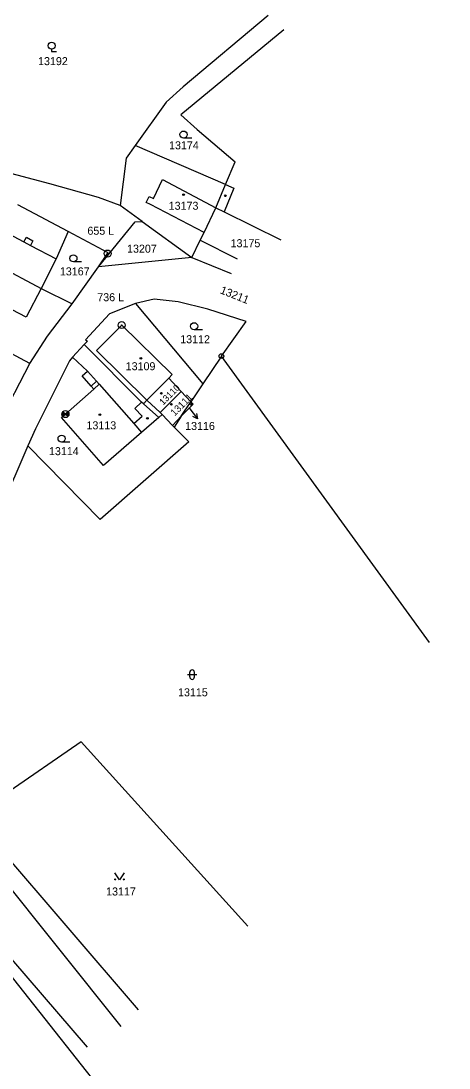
# Model space of a CAD drawing. Extents: x -822293 to -820259, y -1071573 to -1068794.
# Drawn here: x -820500.9 to -820409.9, y -1071370.4 to -1071147.9 of the extents above; entities that cross this region are included whole.
import ezdxf

# ---------------------------------------------------------------- set-up
doc = ezdxf.new("R2010")
doc.units = 0
for name, color, linetype in [('Vrstva 1', 7, 'Continuous'), ('Vrstva 10', 7, 'Continuous'), ('Vrstva 16', 7, 'Continuous'), ('Vrstva 17', 7, 'Continuous'), ('Vrstva 18', 7, 'Continuous'), ('Vrstva 19', 7, 'Continuous'), ('Vrstva 2', 7, 'Continuous'), ('Vrstva 24', 7, 'Continuous'), ('Vrstva 25', 7, 'Continuous'), ('Vrstva 3', 7, 'Continuous'), ('Vrstva 4', 7, 'Continuous')]:
    doc.layers.add(name, color=color, linetype=linetype)

msp = doc.modelspace()

# ---------------------------------------------------------------- linework, layer by layer
at = {"layer": 'Vrstva 1'}
for p, q in [((-820448.39, -1071146.76), (-820466.46, -1071161.95)), ((-820445.03, -1071149.78), (-820466.9, -1071167.9)), ((-820466.46, -1071161.95), (-820470.02, -1071165.17)), ((-820470.02, -1071165.17), (-820476.62, -1071174.38)), ((-820466.9, -1071167.9), (-820463.46, -1071171)), ((-820463.46, -1071171), (-820455.36, -1071177.84)), ((-820476.62, -1071174.38), (-820478.54, -1071177.06)), ((-820457.41, -1071182.67), (-820476.62, -1071174.38)), ((-820478.54, -1071177.06), (-820479.84, -1071187.11)), ((-820457.41, -1071182.67), (-820455.36, -1071177.84)), ((-820494.77, -1071182.54), (-820505.17, -1071179.75)), ((-820484.47, -1071185.46), (-820494.77, -1071182.54)), ((-820479.84, -1071187.11), (-820484.47, -1071185.46)), ((-820500.39, -1071187.63), (-820501.57, -1071187.01)), ((-820490.89, -1071192.65), (-820500.39, -1071187.63)), ((-820475.14, -1071190.53), (-820479.84, -1071187.11)), ((-820484.47, -1071200.14), (-820476.61, -1071190.6)), ((-820476.61, -1071190.6), (-820475.14, -1071190.53)), ((-820475.14, -1071190.53), (-820464.62, -1071198.17)), ((-820490.89, -1071192.65), (-820493.45, -1071198.44)), ((-820482.36, -1071197.15), (-820490.89, -1071192.65)), ((-820464.62, -1071198.17), (-820462.84, -1071194.51)), ((-820484.47, -1071200.14), (-820482.5, -1071197.34)), ((-820482.36, -1071197.15), (-820482.5, -1071197.34)), ((-820464.62, -1071198.17), (-820484.47, -1071200.14)), ((-820464.62, -1071198.17), (-820456.22, -1071201.54)), ((-820490.07, -1071207.98), (-820484.47, -1071200.14)), ((-820496.66, -1071204.76), (-820490.07, -1071207.98)), ((-820495.3, -1071214.89), (-820490.07, -1071207.98)), ((-820476.55, -1071207.91), (-820482.13, -1071210.12)), ((-820472.6, -1071207.05), (-820476.55, -1071207.91)), ((-820476.55, -1071207.91), (-820462.25, -1071225.04)), ((-820467.5, -1071207.56), (-820472.6, -1071207.05)), ((-820461.2, -1071209.17), (-820467.5, -1071207.56)), ((-820482.13, -1071210.12), (-820487.19, -1071215.63)), ((-820453.05, -1071211.75), (-820461.2, -1071209.17)), ((-820499.01, -1071220.67), (-820517.72, -1071210.75)), ((-820458.31, -1071219.13), (-820453.05, -1071211.75)), ((-820499.01, -1071220.67), (-820495.3, -1071214.89)), ((-820487.46, -1071216.64), (-820489.97, -1071219.33)), ((-820486.81, -1071215.95), (-820487.46, -1071216.64)), ((-820475.27, -1071228.92), (-820487.46, -1071216.64)), ((-820487.19, -1071215.63), (-820486.81, -1071215.95)), ((-820489.97, -1071219.33), (-820490.59, -1071220.12)), ((-820486.77, -1071222.33), (-820489.97, -1071219.33)), ((-820458.31, -1071219.13), (-820462.25, -1071225.04)), ((-820414.04, -1071279.95), (-820458.31, -1071219.13)), ((-820505.56, -1071233.12), (-820499.01, -1071220.67)), ((-820490.59, -1071220.12), (-820497.82, -1071234.6)), ((-820487.9, -1071223.33), (-820486.77, -1071222.33)), ((-820486, -1071225.47), (-820487.9, -1071223.33)), ((-820485.43, -1071226.12), (-820486, -1071225.47)), ((-820462.25, -1071225.04), (-820464.77, -1071228.82)), ((-820474.13, -1071228.51), (-820474.9, -1071229.29)), ((-820470.87, -1071231.52), (-820471.62, -1071232.17)), ((-820466.83, -1071231.91), (-820468.35, -1071234.19)), ((-820497.82, -1071234.6), (-820499.47, -1071238.21)), ((-820468.35, -1071234.19), (-820468.7, -1071233.83)), ((-820468.35, -1071234.19), (-820465.21, -1071237.36)), ((-820465.21, -1071237.36), (-820484.08, -1071253.85)), ((-820499.47, -1071238.21), (-820505.24, -1071251.73)), ((-820484.08, -1071253.85), (-820499.47, -1071238.21)), ((-820488.09, -1071301.05), (-820504.37, -1071312.23)), ((-820452.69, -1071340.19), (-820488.09, -1071301.05)), ((-820483.1, -1071375.86), (-820533.17, -1071312.78)), ((-820506.97, -1071321.95), (-820476, -1071357.98))]:
    msp.add_line(p, q, dxfattribs=at)
at = {"layer": 'Vrstva 10'}
msp.add_spline([(-820648.37, -1071145.75), (-820635.21, -1071175.92), (-820619.77, -1071208), (-820606.88, -1071231.72), (-820592.84, -1071254.92), (-820557.31, -1071306.48), (-820522.72, -1071349.67), (-820487.72, -1071388.36), (-820440.04, -1071434.15), (-820382.01, -1071481.32), (-820258.78, -1071573.12)], degree=3, dxfattribs=at)
at = {"layer": 'Vrstva 16'}
msp.add_line((-820465.2, -1071230.04), (-820463.366, -1071232.414), dxfattribs=at)
msp.add_lwpolyline([(-820463.582, -1071231.317), (-820463.366, -1071232.414), (-820464.373, -1071231.929)], dxfattribs=at)
at = {"layer": 'Vrstva 2'}
for p, q in [((-820459.47, -1071187.61), (-820457.41, -1071182.67)), ((-820461.97, -1071192.83), (-820459.47, -1071187.61)), ((-820462.84, -1071194.51), (-820461.97, -1071192.83)), ((-820510.83, -1071197.24), (-820496.66, -1071204.76)), ((-820493.45, -1071198.44), (-820496.66, -1071204.76)), ((-820474.13, -1071228.51), (-820469.47, -1071223.77)), ((-820469.47, -1071223.77), (-820466.83, -1071226.61)), ((-820491.46, -1071231.44), (-820485.43, -1071226.12)), ((-820471.3, -1071231.09), (-820474.13, -1071228.51)), ((-820466.83, -1071226.61), (-820471.3, -1071231.09)), ((-820466.83, -1071226.61), (-820464.77, -1071228.82)), ((-820474.9, -1071229.29), (-820475.27, -1071228.92)), ((-820466.83, -1071231.91), (-820464.77, -1071228.82)), ((-820464.31, -1071229.31), (-820466.83, -1071231.91)), ((-820464.77, -1071228.82), (-820464.31, -1071229.31)), ((-820492.3, -1071232.18), (-820491.46, -1071231.44)), ((-820483.36, -1071242.35), (-820492.3, -1071232.18)), ((-820471.62, -1071232.17), (-820475.27, -1071235.32)), ((-820470.87, -1071231.52), (-820471.3, -1071231.09)), ((-820468.7, -1071233.83), (-820470.87, -1071231.52)), ((-820475.27, -1071235.32), (-820483.36, -1071242.35))]:
    msp.add_line(p, q, dxfattribs=at)
at = {"layer": 'Vrstva 24'}
for p, q in [((-820492.21, -1071231.44), (-820490.71, -1071231.44)), ((-820492.184, -1071231.246), (-820490.736, -1071231.634)), ((-820492.184, -1071231.634), (-820490.736, -1071231.246)), ((-820492.109, -1071231.065), (-820490.811, -1071231.815)), ((-820492.109, -1071231.815), (-820490.811, -1071231.065)), ((-820491.99, -1071231.97), (-820490.93, -1071230.91)), ((-820491.99, -1071230.91), (-820490.93, -1071231.97))]:
    msp.add_line(p, q, dxfattribs=at)
for centre, radius in [((-820482.5, -1071197.34), 0.75), ((-820482.5, -1071197.34), 0.0327), ((-820479.5, -1071212.52), 0.75), ((-820479.5, -1071212.52), 0.0327), ((-820458.31, -1071219.13), 0.5), ((-820458.31, -1071219.13), 0.0327), ((-820491.46, -1071231.44), 0.75)]:
    msp.add_circle(centre, radius, dxfattribs=at)
at = {"layer": 'Vrstva 25'}
for p, q in [((-820494.41, -1071153.93), (-820494.41, -1071154.43)), ((-820494.41, -1071154.43), (-820493.387, -1071154.43)), ((-820464.61, -1071172.81), (-820466.36, -1071172.81)), ((-820488.02, -1071199.1), (-820489.77, -1071199.1)), ((-820462.35, -1071213.52), (-820464.1, -1071213.52)), ((-820490.54, -1071237.39), (-820492.29, -1071237.39)), ((-820465.03, -1071287.28), (-820465.03, -1071286.28)), ((-820464.03, -1071287.28), (-820464.03, -1071286.28)), ((-820465.53, -1071286.78), (-820463.53, -1071286.78))]:
    msp.add_line(p, q, dxfattribs=at)
msp.add_lwpolyline([(-820478.97, -1071328.89), (-820479.97, -1071330.39), (-820480.97, -1071328.89)], dxfattribs=at)
for centre, radius in [((-820494.41, -1071153.18), 0.75), ((-820466.36, -1071172.06), 0.75), ((-820466.36, -1071184.82), 0.175), ((-820457.47, -1071185.06), 0.175), ((-820489.77, -1071198.35), 0.75), ((-820464.1, -1071212.77), 0.75), ((-820475.42, -1071219.58), 0.175), ((-820471.07, -1071227.01), 0.175), ((-820468.95, -1071229.35), 0.175), ((-820464.77, -1071229.35), 0.175), ((-820484.14, -1071231.55), 0.175), ((-820474.03, -1071232.32), 0.175), ((-820492.29, -1071236.64), 0.75), ((-820480.87, -1071330.29), 0.1), ((-820479.07, -1071330.29), 0.1)]:
    msp.add_circle(centre, radius, dxfattribs=at)
for centre, start, end in [((-820464.53, -1071286.28), 0, 180), ((-820464.53, -1071287.28), 180, 0)]:
    msp.add_arc(centre, 0.5, start, end, dxfattribs=at)
at = {"layer": 'Vrstva 3'}
for p, q in [((-820472.76, -1071185.64), (-820470.82, -1071181.61)), ((-820470.82, -1071181.61), (-820459.47, -1071187.61)), ((-820455.64, -1071183.41), (-820457.74, -1071188.47)), ((-820457.41, -1071182.67), (-820455.64, -1071183.41)), ((-820474.27, -1071186.47), (-820473.66, -1071185.2)), ((-820473.66, -1071185.2), (-820472.76, -1071185.64)), ((-820473.37, -1071186.9), (-820474.27, -1071186.47)), ((-820461.97, -1071192.83), (-820473.37, -1071186.9)), ((-820459.47, -1071187.61), (-820457.74, -1071188.47)), ((-820457.74, -1071188.47), (-820445.67, -1071194.43)), ((-820506.49, -1071191.6), (-820500.3, -1071194.85)), ((-820500.3, -1071194.85), (-820498.88, -1071195.6)), ((-820462.84, -1071194.51), (-820454.94, -1071198.48)), ((-820498.88, -1071195.6), (-820493.45, -1071198.44)), ((-820499.85, -1071210.87), (-820514.02, -1071203.33)), ((-820496.66, -1071204.76), (-820499.85, -1071210.87)), ((-820484.85, -1071217.96), (-820479.5, -1071212.52)), ((-820479.5, -1071212.52), (-820468.76, -1071223.06)), ((-820484.85, -1071217.96), (-820474.13, -1071228.51)), ((-820468.76, -1071223.06), (-820469.47, -1071223.77)), ((-820485.43, -1071226.12), (-820484.29, -1071225.11)), ((-820484.29, -1071225.11), (-820476.92, -1071233.45)), ((-820476.7, -1071230.22), (-820475.27, -1071228.92)), ((-820475.12, -1071231.85), (-820476.7, -1071230.22)), ((-820474.9, -1071229.29), (-820471.62, -1071232.17)), ((-820476.92, -1071233.45), (-820475.12, -1071231.85)), ((-820468.7, -1071233.83), (-820466.83, -1071231.91)), ((-820476.92, -1071233.45), (-820475.27, -1071235.32))]:
    msp.add_line(p, q, dxfattribs=at)
at = {"layer": 'Vrstva 4'}
for p, q in [((-820500.3, -1071194.85), (-820499.78, -1071193.88)), ((-820499.78, -1071193.88), (-820498.37, -1071194.62)), ((-820498.37, -1071194.62), (-820498.88, -1071195.6)), ((-820486.77, -1071222.33), (-820484.87, -1071224.44)), ((-820484.87, -1071224.44), (-820486, -1071225.47)), ((-820484.87, -1071224.44), (-820484.29, -1071225.11)), ((-820540.54, -1071285.54), (-820479.66, -1071361.53)), ((-820486.8, -1071365.91), (-820547.67, -1071295.15))]:
    msp.add_line(p, q, dxfattribs=at)

# ---------------------------------------------------------------- texts
at = {"layer": 'Vrstva 16'}
msp.add_text('13116', height=1.7, dxfattribs=at).set_placement((-820466.016, -1071234.81))
at = {"layer": 'Vrstva 17'}
for s, p in [('655 L', (-820486.793, -1071193.34)), ('736 L', (-820484.696, -1071207.46))]:
    msp.add_text(s, height=1.7, dxfattribs=at).set_placement(p)
at = {"layer": 'Vrstva 18'}
for s, p in [('13192', (-820497.288, -1071157.31)), ('13174', (-820469.438, -1071175.19)), ('13207', (-820478.364, -1071197.15)), ('13167', (-820492.648, -1071201.97)), ('13112', (-820467.062, -1071216.38)), ('13114', (-820494.966, -1071240.16)), ('13115', (-820467.528, -1071291.38)), ('13117', (-820482.821, -1071333.69))]:
    msp.add_text(s, height=1.7, dxfattribs=at).set_placement(p)
msp.add_text('13211', height=1.7, rotation=338.35956, dxfattribs=at).set_placement((-820458.713, -1071205.74))
at = {"layer": 'Vrstva 19'}
for s, p in [('13173', (-820469.515, -1071188.03)), ('13175', (-820456.35, -1071195.99)), ('13109', (-820478.657, -1071222.12)), ('13113', (-820486.994, -1071234.67))]:
    msp.add_text(s, height=1.7, dxfattribs=at).set_placement(p)
for s, height, rotation, p in [('13110', 1.4, 45.08118, (-820470.683, -1071229.656)), ('13111', 1.5, 45.08118, (-820468.233, -1071231.966)), ('13116', 0.024, 45.8505, (-820465.217, -1071230.058))]:
    msp.add_text(s, height=height, rotation=rotation, dxfattribs=at).set_placement(p)

doc.saveas('drawing.dxf')
